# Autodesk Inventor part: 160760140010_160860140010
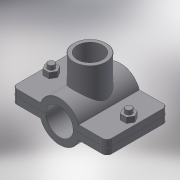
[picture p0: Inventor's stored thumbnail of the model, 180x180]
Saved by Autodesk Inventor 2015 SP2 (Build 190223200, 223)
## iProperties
Created: 2017-05
Part Number: 160760140010_160860140010
Material: Generic
Description: PLASSON SADDLE 140-1"
Document SubType Name: Modeling
Designer: KIM
Density: 1 g/cm^3
Appearance: Default
Author: KIM
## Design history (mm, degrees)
derived "16076.ipt"
feature "Solid1::16076.ipt"
feature "Solid2::16076.ipt"
tag "TaggingFeature1"
body "Solid1"
other parameters: "d0" = 154, "d1" = 201, "d4" = 136, "d5" = 0, "d6" = 10.05, "d7" = 201, "d8" = 0.1, "d10" = 0, "d11" = 1.4, "d14" = 39.3783, "d20" = 1.4, "d23" = 1.4, "d36" = 15, "d37" = 12, "d38" = 78, "d39" = 0, "d40" = 3, "d41" = 5, "d42" = 0, "d44" = 3, "d45" = 0, "d46" = 1.4, "d51" = 101, "d52" = 30.291, "d53" = 21, "d54" = 0, "d55" = 25, "d57" = 0, "d58" = 151.2, "d60" = 0, "d62" = 15, "d63" = 12, "d66" = 112, "B_" = 25, "G_" = 30.291, "A_" = 101, "L_" = 201, "L_1" = 136, "l_2" = 21
